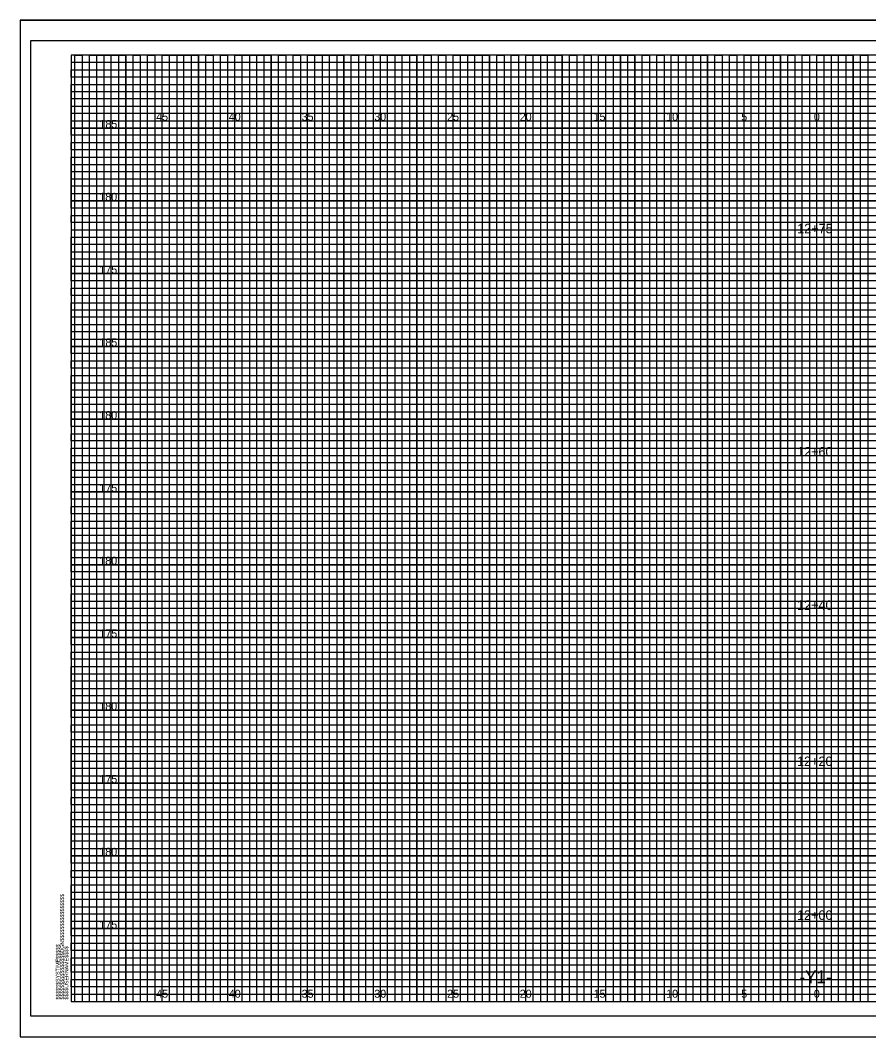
# Model space of a CAD drawing. Extents: x -4 to 103, y -2 to 209.
# Drawn here: x -3.5 to 54.8, y -2.4 to 67.4 of the extents above; entities that cross this region are included whole.
import ezdxf

# ---------------------------------------------------------------- set-up
doc = ezdxf.new("R2010")
doc.units = 0
for name, color, linetype in [('Old_Level_10', 7, 'Continuous'), ('Old_Level_16', 7, 'Continuous'), ('Old_Level_3', 7, 'Continuous'), ('Old_Level_4', 7, 'Continuous'), ('Old_Level_5', 7, 'Continuous'), ('Old_Level_6', 7, 'Continuous'), ('Old_Level_8', 7, 'Continuous'), ('Prop Dimension', 7, 'Continuous'), ('Prop XS Dump Level', 7, 'Continuous'), ('Prop XS Finish Grade Pavement', 7, 'Continuous'), ('Prop XS Subgrade Earthwork', 7, 'Continuous')]:
    doc.layers.add(name, color=color, linetype=linetype)

msp = doc.modelspace()

# ---------------------------------------------------------------- linework, layer by layer
at = {"layer": 'Old_Level_10'}
for p, q in [((1.25, 0), (1.25, 65)), ((3.75, 0), (3.75, 65)), ((6.25, 0), (6.25, 65)), ((8.75, 0), (8.75, 65)), ((11.25, 0), (11.25, 65)), ((13.75, 0), (13.75, 65)), ((16.25, 0), (16.25, 65)), ((18.75, 0), (18.75, 65)), ((21.25, 0), (21.25, 65)), ((23.75, 0), (23.75, 65)), ((26.25, 0), (26.25, 65)), ((28.75, 0), (28.75, 65)), ((31.25, 0), (31.25, 65)), ((33.75, 0), (33.75, 65)), ((36.25, 0), (36.25, 65)), ((38.75, 0), (38.75, 65)), ((41.25, 0), (41.25, 65)), ((43.75, 0), (43.75, 65)), ((46.25, 0), (46.25, 65)), ((48.75, 0), (48.75, 65)), ((51.25, 0), (51.25, 65)), ((53.75, 0), (53.75, 65)), ((0, 62.5), (74.25, 62.5)), ((0, 60), (102.5, 60)), ((0, 57.5), (102.5, 57.5)), ((0, 55), (102.5, 55)), ((0, 52.5), (102.5, 52.5)), ((0, 50), (102.5, 50)), ((0, 47.5), (102.5, 47.5)), ((0, 45), (102.5, 45)), ((0, 42.5), (102.5, 42.5)), ((0, 40), (102.5, 40)), ((0, 37.5), (102.5, 37.5)), ((0, 35), (102.5, 35)), ((0, 32.5), (102.5, 32.5)), ((0, 30), (102.5, 30)), ((0, 27.5), (102.5, 27.5)), ((0, 25), (102.5, 25)), ((0, 22.5), (102.5, 22.5)), ((0, 20), (102.5, 20)), ((0, 17.5), (102.5, 17.5)), ((0, 15), (102.5, 15)), ((0, 12.5), (102.5, 12.5)), ((0, 10), (102.5, 10)), ((0, 7.5), (102.5, 7.5)), ((0, 5), (102.5, 5)), ((0, 2.5), (102.5, 2.5))]:
    msp.add_line(p, q, dxfattribs=at)
at = {"layer": 'Old_Level_3'}
for p, q in [((-3.5, 67.4), (103.4, 67.4)), ((-3.5, 67.4), (-3.5, -2.425)), ((-3.5, -2.425), (103.4, -2.425))]:
    msp.add_line(p, q, dxfattribs=at)
at = {"layer": 'Old_Level_4'}
msp.add_lwpolyline([(103, 66), (-2.8, 66), (-2.8, -1), (103, -1)], close=True, dxfattribs=at)
at = {"layer": 'Old_Level_5'}
msp.add_lwpolyline([(103.4, 67.4), (-3.5, 67.4), (-3.5, -2.425), (103.4, -2.425)], close=True, dxfattribs=at)
at = {"layer": 'Old_Level_6'}
msp.add_lwpolyline([(102.5, 65), (0, 65), (0, 0), (102.5, 0)], close=True, dxfattribs=at)
at = {"layer": 'Old_Level_8'}
for points in [[(1.25, 0), (1.25, 65), (3.75, 65), (3.75, 0), (6.25, 0), (6.25, 65), (8.75, 65), (8.75, 0), (11.25, 0), (11.25, 65), (13.75, 65), (13.75, 0), (16.25, 0), (16.25, 65), (18.75, 65), (18.75, 0), (21.25, 0), (21.25, 65), (23.75, 65), (23.75, 0), (26.25, 0), (26.25, 65), (28.75, 65), (28.75, 0), (31.25, 0), (31.25, 65), (33.75, 65), (33.75, 0), (36.25, 0), (36.25, 65), (38.75, 65), (38.75, 0), (41.25, 0), (41.25, 65), (43.75, 65), (43.75, 0), (46.25, 0), (46.25, 65), (48.75, 65), (48.75, 0), (51.25, 0), (51.25, 65), (53.75, 65), (53.75, 0)], [(102.5, 60), (0, 60), (0, 62.5), (74.25, 62.5)], [(102.5, 55), (0, 55), (0, 57.5), (102.5, 57.5)], [(102.5, 50), (0, 50), (0, 52.5), (102.5, 52.5)], [(102.5, 45), (0, 45), (0, 47.5), (102.5, 47.5)], [(102.5, 40), (0, 40), (0, 42.5), (102.5, 42.5)], [(102.5, 35), (0, 35), (0, 37.5), (102.5, 37.5)], [(102.5, 30), (0, 30), (0, 32.5), (102.5, 32.5)], [(102.5, 25), (0, 25), (0, 27.5), (102.5, 27.5)], [(102.5, 20), (0, 20), (0, 22.5), (102.5, 22.5)], [(102.5, 15), (0, 15), (0, 17.5), (102.5, 17.5)], [(102.5, 10), (0, 10), (0, 12.5), (102.5, 12.5)], [(102.5, 5), (0, 5), (0, 7.5), (102.5, 7.5)], [(0, 2.5), (102.5, 2.5)]]:
    msp.add_lwpolyline(points, dxfattribs=at)
at = {"layer": 'Prop Dimension'}
for points in [[(0.25, 0), (0.25, 65), (0.75, 65), (0.75, 0), (1.75, 0), (1.75, 65), (2.25, 65), (2.25, 0), (2.75, 0), (2.75, 65), (3.25, 65), (3.25, 0), (4.25, 0), (4.25, 65), (4.75, 65), (4.75, 0), (5.25, 0), (5.25, 65), (5.75, 65), (5.75, 0), (6.75, 0), (6.75, 65), (7.25, 65), (7.25, 0), (7.75, 0), (7.75, 65), (8.25, 65), (8.25, 0), (9.25, 0), (9.25, 65), (9.75, 65), (9.75, 0), (10.25, 0), (10.25, 65), (10.75, 65), (10.75, 0), (11.75, 0), (11.75, 65), (12.25, 65), (12.25, 0), (12.75, 0), (12.75, 65), (13.25, 65), (13.25, 0), (14.25, 0), (14.25, 65), (14.75, 65), (14.75, 0), (15.75, 0), (15.25, 0), (15.25, 65), (15.75, 65), (15.75, 0), (16.75, 0), (16.75, 65), (17.25, 65), (17.25, 0), (17.75, 0), (17.75, 65), (18.25, 65), (18.25, 0), (19.25, 0), (19.25, 65), (19.75, 65), (19.75, 0), (20.25, 0), (20.25, 65), (20.75, 65), (20.75, 0), (21.75, 0), (21.75, 65), (22.25, 65), (22.25, 0), (22.75, 0), (22.75, 65), (23.25, 65), (23.25, 0), (24.25, 0), (24.25, 65), (24.75, 65), (24.75, 0), (25.25, 0), (25.25, 65), (25.75, 65), (25.75, 0), (26.75, 0), (26.75, 65), (27.25, 65), (27.25, 0), (27.75, 0), (27.75, 65), (28.25, 65), (28.25, 0), (29.25, 0), (29.25, 65), (29.75, 65), (29.75, 0), (30.25, 0), (30.25, 65), (30.75, 65), (30.75, 0)], [(30.75, 0), (31.75, 0), (31.75, 65), (32.25, 65), (32.25, 0), (32.75, 0), (32.75, 65), (33.25, 65), (33.25, 0), (34.25, 0), (34.25, 65), (34.75, 65), (34.75, 0), (35.25, 0), (35.25, 65), (35.75, 65), (35.75, 0), (36.75, 0), (36.75, 65), (37.25, 65), (37.25, 0), (37.75, 0), (37.75, 65), (37.75, 0)], [(38.25, 65), (38.25, 0), (39.25, 0), (39.25, 65), (39.75, 65), (39.75, 0), (40.25, 0), (40.25, 65), (40.75, 65), (40.75, 0), (41.75, 0), (41.75, 65), (42.25, 65), (42.25, 0), (42.75, 0), (42.75, 65), (43.25, 65), (43.25, 0), (43.75, 0), (44.25, 0), (44.25, 65), (44.75, 65), (44.75, 0), (45.25, 0), (45.25, 65), (45.75, 65), (45.75, 0), (46.75, 0), (46.75, 65), (47.25, 65), (47.25, 0), (47.75, 0), (47.75, 65), (48.25, 65), (48.25, 0), (49.25, 0), (49.25, 65), (49.75, 65), (49.75, 0), (50.25, 0), (50.25, 65), (50.75, 65), (50.75, 0), (51.75, 0), (51.75, 65), (52.25, 65), (52.25, 0), (52.75, 0), (52.75, 65), (53.25, 65), (53.25, 0), (54.25, 0), (54.25, 65), (54.75, 65), (54.75, 0), (55.25, 0)], [(0, 62), (0, 63), (74.25, 63), (74.25, 63.5), (0, 63.5), (0, 64), (74.25, 64), (74.25, 64.5), (0, 64.5)], [(102.5, 62), (0, 62)], [(102.5, 61), (0, 61), (0, 61.5), (102.5, 61.5)], [(102.5, 59.5), (0, 59.5), (0, 60.5), (102.5, 60.5)], [(102.5, 58.5), (0, 58.5), (0, 59), (102.5, 59)], [(102.5, 57), (0, 57), (0, 58), (102.5, 58)], [(102.5, 56), (0, 56), (0, 56.5), (102.5, 56.5)], [(102.5, 54.5), (0, 54.5), (0, 55.5), (102.5, 55.5)], [(102.5, 53.5), (0, 53.5), (0, 54), (102.5, 54)], [(0, 53), (102.5, 53)], [(102.5, 52), (0, 52)], [(102.5, 51), (0, 51), (0, 51.5), (102.5, 51.5)], [(102.5, 49.5), (0, 49.5), (0, 50.5), (102.5, 50.5)], [(102.5, 48.5), (0, 48.5), (0, 49), (102.5, 49)], [(102.5, 47), (0, 47), (0, 48), (102.5, 48)], [(102.5, 46), (0, 46), (0, 46.5), (102.5, 46.5)], [(102.5, 44.5), (0, 44.5), (0, 45.5), (102.5, 45.5)], [(102.5, 43.5), (0, 43.5), (0, 44), (102.5, 44)], [(102.5, 42), (0, 42), (0, 43), (102.5, 43)], [(102.5, 41), (0, 41), (0, 41.5), (102.5, 41.5)], [(102.5, 39.5), (0, 39.5), (0, 40.5), (102.5, 40.5)], [(102.5, 38.5), (0, 38.5), (0, 39), (102.5, 39)], [(102.5, 37), (0, 37), (0, 38), (102.5, 38)], [(102.5, 36), (0, 36), (0, 36.5), (102.5, 36.5)], [(102.5, 34.5), (0, 34.5), (0, 35.5), (102.5, 35.5)], [(102.5, 33.5), (0, 33.5), (0, 34), (102.5, 34)], [(102.5, 32), (0, 32), (0, 33), (102.5, 33)], [(102.5, 31), (0, 31), (0, 31.5)], [(0, 31.5), (102.5, 31.5)], [(102.5, 29.5), (0, 29.5), (0, 30.5), (102.5, 30.5)], [(102.5, 28.5), (0, 28.5), (0, 29), (102.5, 29)], [(102.5, 27), (0, 27), (0, 28), (102.5, 28)], [(102.5, 26), (0, 26), (0, 26.5), (102.5, 26.5)], [(102.5, 24.5), (0, 24.5), (0, 25.5), (102.5, 25.5)], [(102.5, 23.5), (0, 23.5), (0, 24), (102.5, 24)], [(102.5, 22), (0, 22), (0, 23), (102.5, 23)], [(102.5, 21), (0, 21), (0, 21.5), (102.5, 21.5)], [(102.5, 19.5), (0, 19.5), (0, 20.5), (102.5, 20.5)], [(102.5, 18.5), (0, 18.5), (0, 19), (102.5, 19)], [(102.5, 17), (0, 17), (0, 18), (102.5, 18)], [(102.5, 16), (0, 16), (0, 16.5), (102.5, 16.5)], [(102.5, 14.5), (0, 14.5), (0, 15.5), (102.5, 15.5)], [(102.5, 13.5), (0, 13.5), (0, 14), (102.5, 14)], [(102.5, 12), (0, 12), (0, 13), (102.5, 13)], [(102.5, 11), (0, 11), (0, 11.5), (102.5, 11.5)], [(102.5, 9.5), (0, 9.5), (0, 10.5), (102.5, 10.5)], [(102.5, 8.5), (0, 8.5), (0, 9), (102.5, 9)], [(102.5, 7), (0, 7), (0, 8), (102.5, 8)], [(102.5, 6), (0, 6), (0, 6.5), (102.5, 6.5)], [(102.5, 4.5), (0, 4.5), (0, 5.5), (102.5, 5.5)], [(102.5, 3.5), (0, 3.5), (0, 4), (102.5, 4)], [(102.5, 2), (0, 2), (0, 3), (102.5, 3)], [(102.5, 1), (0, 1), (0, 1.5), (102.5, 1.5)], [(0, 0.5), (102.5, 0.5)]]:
    msp.add_lwpolyline(points, dxfattribs=at)

# ---------------------------------------------------------------- texts
at = {"layer": 'Old_Level_16'}
for s, p in [('45', (5.8399, 60.5)), ('40', (10.8313, 60.5)), ('35', (15.8399, 60.5)), ('30', (20.8313, 60.5)), ('25', (25.8399, 60.5)), ('20', (30.8313, 60.5)), ('15', (35.9058, 60.5)), ('10', (40.8971, 60.5)), ('5', (46.0574, 60.5)), ('0', (51.0488, 60.5)), ('0', (51.0488, 60.5)), ('45', (5.8399, 0.25)), ('40', (10.8313, 0.25)), ('35', (15.8399, 0.25)), ('30', (20.8313, 0.25)), ('25', (25.8399, 0.25)), ('20', (30.8313, 0.25)), ('15', (35.9058, 0.25)), ('10', (40.8971, 0.25)), ('5', (46.0574, 0.25)), ('0', (51.0488, 0.25)), ('0', (51.0488, 0.25))]:
    msp.add_text(s, height=0.55, dxfattribs=at).set_placement(p)
at = {"layer": 'Old_Level_6'}
for s, p in [('$$$$$$$$$$$$$$$$DGN$$$$$$$$$$$$$$$$', (-0.5, 0.125)), ('$$$$$$SYSTIME$$$$$', (-0.7973, 0.1247)), ('$$$$USERNAME$$$$', (-0.2, 0.125))]:
    msp.add_text(s, height=0.2625, rotation=90, dxfattribs=at).set_placement(p)
at = {"layer": 'Old_Level_8'}
msp.add_text('040397', height=0.0025, rotation=90, dxfattribs=at).set_placement((-0.0007, 64.9864))
at = {"layer": 'Prop XS Dump Level'}
msp.add_text('-Y1-', height=0.875, dxfattribs=at).set_placement((50.0581, 1.25))
at = {"layer": 'Prop XS Finish Grade Pavement'}
for s, p in [('12+75', (49.9036, 52.7704)), ('12+60', (49.8934, 37.4364)), ('12+40', (49.8934, 26.8982)), ('12+20', (49.8934, 16.1686)), ('12+00', (49.8934, 5.5999))]:
    msp.add_text(s, height=0.65, dxfattribs=at).set_placement(p)
at = {"layer": 'Prop XS Subgrade Earthwork'}
for s, p in [('185', (1.9383, 60)), ('180', (1.9296, 55)), ('175', (1.9383, 50)), ('185', (1.9383, 45)), ('180', (1.9296, 40)), ('175', (1.9383, 35)), ('180', (1.9296, 30)), ('175', (1.9383, 25)), ('180', (1.9296, 20)), ('175', (1.9383, 15)), ('180', (1.9296, 10)), ('175', (1.9383, 5))]:
    msp.add_text(s, height=0.55, dxfattribs=at).set_placement(p)

doc.saveas('drawing.dxf')
